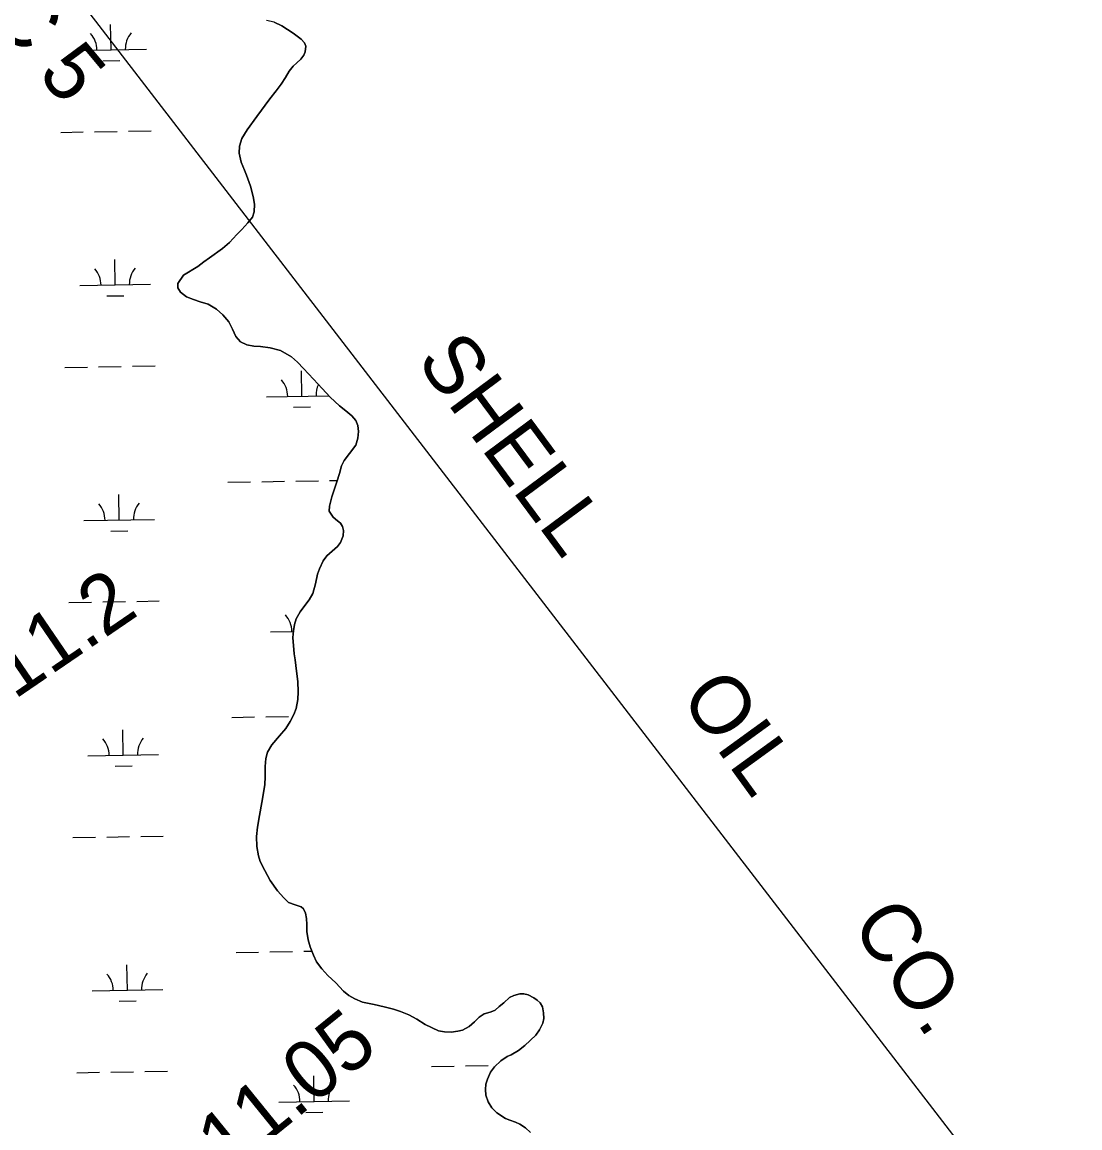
# Model space of a CAD drawing. Extents: x 3892998 to 3931244, y 278583 to 304547.
# Drawn here: x 3913620 to 3915117, y 291060 to 292624 of the extents above; entities that cross this region are included whole.
import ezdxf

# ---------------------------------------------------------------- set-up
doc = ezdxf.new("R2010")
doc.units = 0
for name, color, linetype in [('V-RIVR-EDGE', 7, 'Continuous'), ('V-RIVR-RANG-IDEN', 7, 'Continuous'), ('V-TOPO-SHOR', 7, 'Continuous'), ('V-UTIL-IDEN', 7, 'Continuous'), ('V-UTIL-LINE', 7, 'Continuous'), ('V-WETL-SWMP', 7, 'Continuous')]:
    doc.layers.add(name, color=color, linetype=linetype)

msp = doc.modelspace()

# ---------------------------------------------------------------- linework, layer by layer
at = {"layer": 'V-RIVR-EDGE'}
msp.add_spline([(3912905.5, 291820.1), (3912916.2, 291798.1), (3912921.4, 291787), (3912931.4, 291765), (3912935.9, 291747.6), (3912940.4, 291735.8), (3912955, 291711.4), (3912961.5, 291684.5), (3912964.3, 291665.7), (3912967, 291653.5), (3912976, 291634.4), (3912985.7, 291613.1), (3912986.4, 291604.4), (3912990.5, 291597.4), (3912997.1, 291593.3), (3913007.6, 291587), (3913014.2, 291580.7), (3913019.4, 291567.4), (3913027, 291556.3), (3913048.2, 291537.1), (3913061.4, 291520.7), (3913079.1, 291496.6), (3913103, 291468.4), (3913127.3, 291438.4), (3913184.9, 291379.7), (3913206.1, 291354.6), (3913225.2, 291327.8), (3913253.3, 291286.6), (3913265.1, 291274.8), (3913279.3, 291262.2), (3913304.7, 291231.5), (3913329.3, 291201.2), (3913355.7, 291168.4), (3913376.5, 291143.3), (3913400.8, 291111.5), (3913434.5, 291068.6), (3913468.5, 291022.2), (3913495.2, 290985.6), (3913514.6, 290959.1), (3913570.4, 290873.7), (3913590.9, 290842), (3913606.5, 290820.3), (3913627.3, 290792.1), (3913641.2, 290769.8), (3913669.6, 290726.2), (3913686.6, 290700.8), (3913705.7, 290679.5), (3913722, 290663.1), (3913741.1, 290638), (3913763.7, 290606.9), (3913781, 290589.5)], degree=3, dxfattribs=at)
at = {"layer": 'V-TOPO-SHOR'}
for points in [[(3913872.1, 292228.6), (3913862.7, 292231.7), (3913852.9, 292235.6), (3913844.3, 292242.1), (3913840.6, 292248.5), (3913840.3, 292254.7), (3913848.4, 292266.4), (3913868.7, 292278.5), (3913877.2, 292285), (3913885.1, 292291), (3913903.7, 292304), (3913913.4, 292312.7), (3913924, 292324), (3913930.9, 292331), (3913939.7, 292340.4), (3913946, 292348.3), (3913948.4, 292356), (3913948.7, 292366.6), (3913947, 292377.6), (3913943.3, 292392.2), (3913937.5, 292407.9), (3913934.6, 292414.9), (3913930.3, 292426.3), (3913927.3, 292439), (3913927.5, 292448.9), (3913931, 292459.6), (3913938.5, 292472.2), (3913952.2, 292490.9), (3913970.4, 292515.8), (3913979.7, 292527.1), (3913986.8, 292536.5), (3913992.8, 292546), (3913998.1, 292554.8), (3914003.8, 292562), (3914008.8, 292566.9), (3914014.3, 292571.9), (3914018.7, 292577.4), (3914020.7, 292582.4), (3914021.4, 292590.2), (3914019.5, 292595), (3914014.8, 292600.3), (3914003.7, 292608.8), (3913987.6, 292619.2), (3913976.7, 292624.4), (3913965.8, 292626.7)], [(3914075, 291253.5), (3914064, 291265), (3914052.9, 291275.6), (3914044.1, 291284.9), (3914036.9, 291294.8), (3914032.2, 291304), (3914027.6, 291315.8), (3914024.7, 291325.9), (3914023, 291337.8), (3914022.9, 291347.8), (3914022.7, 291356.2), (3914021.3, 291363.5), (3914018.5, 291369.7), (3914014.8, 291372.6), (3914006.6, 291375.3), (3913997.2, 291378.9), (3913990.5, 291385.4), (3913981.6, 291395.1), (3913970.9, 291409.8), (3913963.4, 291423.9), (3913956.9, 291436.7), (3913954.4, 291444.9), (3913952.2, 291458.1), (3913951.8, 291472.3), (3913953, 291485.3), (3913955.8, 291501.9), (3913959.5, 291520.1), (3913963.4, 291545), (3913964, 291557.1), (3913964.2, 291571.2), (3913965.2, 291582.3), (3913967.5, 291591.4), (3913973.4, 291601.6), (3913984.3, 291614.7), (3913993.2, 291624.9), (3913999.5, 291634.8), (3914004.8, 291644.5), (3914007.7, 291653), (3914010.1, 291666), (3914010.7, 291677), (3914010.4, 291691.5), (3914008.5, 291706.1), (3914006.3, 291721.9), (3914004.9, 291730.7), (3914003.3, 291753.8), (3914004, 291762.9), (3914005.4, 291771.9), (3914007.8, 291779.9), (3914013.4, 291789.8), (3914021.5, 291801), (3914026.5, 291807.1), (3914031.5, 291815.9), (3914035.2, 291829.5), (3914038.3, 291843.1), (3914041.1, 291850.9), (3914046.1, 291862.3), (3914051.4, 291869.3), (3914058.6, 291875.8), (3914066.2, 291882.4), (3914070.6, 291888.3), (3914074.4, 291897.7), (3914075, 291905.2), (3914073.6, 291910.6), (3914070.6, 291915.3), (3914066.4, 291918.9), (3914060.2, 291923.9), (3914054.8, 291932.2), (3914055.1, 291939.7), (3914058.3, 291952.6), (3914065.3, 291973.7), (3914069, 291985.7), (3914072.2, 291996.6), (3914075.6, 292004.3), (3914083.4, 292014), (3914092.1, 292025.7), (3914095.1, 292035.6), (3914095.9, 292045), (3914095.3, 292053.7), (3914092.4, 292060.9), (3914086.7, 292067.5), (3914078, 292074.4), (3914069.2, 292081.5), (3914055.9, 292093.9), (3914044.5, 292106.2), (3914032.5, 292119.3), (3914018.4, 292134.1), (3914009.6, 292143.2), (3914001.1, 292150.8), (3913985.6, 292159.7), (3913971.3, 292163.6), (3913957.6, 292165.2), (3913947.9, 292165.8), (3913938.2, 292167.8), (3913928.9, 292172.2), (3913922.6, 292179.5), (3913917.7, 292189.8), (3913912.6, 292200.2), (3913904.3, 292210.3), (3913895.3, 292218), (3913883.2, 292225.1), (3913872.1, 292228.6)], [(3914339.5, 291053.2), (3914332.5, 291059.8), (3914324.3, 291065.1), (3914318.1, 291068.1), (3914310.4, 291070.6), (3914304.1, 291073.2), (3914292, 291081), (3914284.7, 291088.3), (3914279.5, 291096.6), (3914276.5, 291106.2), (3914275.8, 291114), (3914276.5, 291121.6), (3914278.5, 291128.8), (3914283, 291138.7), (3914288.4, 291146.3), (3914297.5, 291154.5), (3914306.4, 291160.9), (3914312.2, 291163.4), (3914322.4, 291169.2), (3914331.5, 291176.4), (3914346.9, 291191), (3914352.4, 291198.7), (3914357, 291208.1), (3914358.3, 291214.5), (3914358.1, 291222.7), (3914356.4, 291230.9), (3914353.3, 291236.8), (3914349.1, 291240.6), (3914344.2, 291244), (3914336.4, 291248), (3914329.9, 291249.7), (3914324.4, 291249.4), (3914316.1, 291247), (3914310, 291244.3), (3914301.6, 291237), (3914295.2, 291231.4), (3914289.4, 291226.6), (3914284, 291224.1), (3914279.1, 291222.8), (3914273.7, 291221), (3914266.9, 291216.6), (3914260.2, 291209.9), (3914252.5, 291203.3), (3914243.4, 291198), (3914236.8, 291196.5), (3914227.4, 291195.4), (3914218, 291195.8), (3914209.4, 291197.2), (3914190.6, 291205.9), (3914178.8, 291213.5), (3914167.3, 291219.9), (3914155.6, 291224.7), (3914145.8, 291228), (3914132.4, 291230.9), (3914118.4, 291234.2), (3914101.9, 291237.9), (3914090.7, 291242.3), (3914082.2, 291247.3), (3914075, 291253.5)]]:
    msp.add_lwpolyline(points, dxfattribs=at)
at = {"layer": 'V-UTIL-LINE'}
msp.add_lwpolyline([(3906680.9, 302363.5), (3908344.9, 300090), (3912732.6, 293653.7), (3913646.8, 292726.8), (3916248.7, 289346), (3918159.9, 287579.4), (3921518.3, 284435.1)], dxfattribs=at)
at = {"layer": 'V-WETL-SWMP'}
for p, q in [((3913746.1, 292585.1), (3913745.4, 292621.1)), ((3913976.7, 292624.4), (3913987.6, 292619.2)), ((3913987.6, 292619.2), (3914003.7, 292608.8)), ((3914003.7, 292608.8), (3914014.8, 292600.3)), ((3914014.8, 292600.3), (3914019.5, 292595)), ((3914019.5, 292595), (3914021.4, 292590.2)), ((3914021.4, 292590.2), (3914020.7, 292582.4)), ((3913696.1, 292584.3), (3913796.1, 292586)), ((3914014.3, 292571.9), (3914008.8, 292566.9)), ((3914018.7, 292577.4), (3914014.3, 292571.9)), ((3914020.7, 292582.4), (3914018.7, 292577.4)), ((3913734.3, 292569.5), (3913758.3, 292569.9)), ((3914003.8, 292562), (3913998.1, 292554.8)), ((3914008.8, 292566.9), (3914003.8, 292562)), ((3913992.8, 292546), (3913986.8, 292536.5)), ((3913998.1, 292554.8), (3913992.8, 292546)), ((3913979.7, 292527.1), (3913970.4, 292515.8)), ((3913986.8, 292536.5), (3913979.7, 292527.1)), ((3913970.4, 292515.8), (3913952.2, 292490.9)), ((3913952.2, 292490.9), (3913938.5, 292472.2)), ((3913674.7, 292468.4), (3913706.7, 292469)), ((3913722.7, 292469.3), (3913754.7, 292469.8)), ((3913770.7, 292470.1), (3913802.6, 292470.6)), ((3913938.5, 292472.2), (3913931, 292459.6)), ((3913927.5, 292448.9), (3913927.3, 292439)), ((3913931, 292459.6), (3913927.5, 292448.9)), ((3913927.3, 292439), (3913930.3, 292426.3)), ((3913930.3, 292426.3), (3913934.6, 292414.9)), ((3913934.6, 292414.9), (3913937.5, 292407.9)), ((3913937.5, 292407.9), (3913943.3, 292392.2)), ((3913943.3, 292392.2), (3913947, 292377.6)), ((3913947, 292377.6), (3913948.7, 292366.6)), ((3913948.4, 292356), (3913946, 292348.3)), ((3913948.7, 292366.6), (3913948.4, 292356)), ((3913939.7, 292340.4), (3913930.9, 292331)), ((3913946, 292348.3), (3913939.7, 292340.4)), ((3913924, 292324), (3913913.4, 292312.7)), ((3913930.9, 292331), (3913924, 292324)), ((3913913.4, 292312.7), (3913903.7, 292304)), ((3913905.5, 292305.9), (3913905.8, 292305.9)), ((3913885.1, 292291), (3913877.2, 292285)), ((3913903.7, 292304), (3913885.1, 292291)), ((3913751.8, 292252.5), (3913751.2, 292288.5)), ((3913868.7, 292278.5), (3913848.4, 292266.4)), ((3913877.2, 292285), (3913868.7, 292278.5)), ((3913848.4, 292266.4), (3913840.3, 292254.7)), ((3913701.8, 292251.6), (3913801.8, 292253.4)), ((3913840.3, 292254.7), (3913840.6, 292248.5)), ((3913840.6, 292248.5), (3913844.3, 292242.1)), ((3913740.1, 292236.9), (3913764.1, 292237.3)), ((3913844.3, 292242.1), (3913852.9, 292235.6)), ((3913852.9, 292235.6), (3913862.7, 292231.7)), ((3913862.7, 292231.7), (3913872.1, 292228.6)), ((3913872.1, 292228.6), (3913883.2, 292225.1)), ((3913883.2, 292225.1), (3913895.3, 292218)), ((3913895.3, 292218), (3913904.3, 292210.3)), ((3913904.3, 292210.3), (3913912.6, 292200.2)), ((3913912.6, 292200.2), (3913917.7, 292189.8)), ((3913917.7, 292189.8), (3913922.6, 292179.5)), ((3913922.6, 292179.5), (3913928.9, 292172.2)), ((3913928.9, 292172.2), (3913938.2, 292167.8)), ((3913938.2, 292167.8), (3913947.9, 292165.8)), ((3913947.9, 292165.8), (3913957.6, 292165.2)), ((3913957.6, 292165.2), (3913971.3, 292163.6)), ((3913971.3, 292163.6), (3913985.6, 292159.7)), ((3913985.6, 292159.7), (3914001.1, 292150.8)), ((3914001.1, 292150.8), (3914009.6, 292143.2)), ((3913680.4, 292135.8), (3913712.4, 292136.4)), ((3913728.4, 292136.6), (3913760.4, 292137.2)), ((3913776.4, 292137.5), (3913808.4, 292138)), ((3914009.6, 292143.2), (3914018.4, 292134.1)), ((3914018.4, 292134.1), (3914032.5, 292119.3)), ((3914016, 292095.2), (3914015.4, 292131.2)), ((3914032.5, 292119.3), (3914044.5, 292106.2)), ((3914044.5, 292106.2), (3914055.9, 292093.9)), ((3913966, 292094.3), (3914054.1, 292095.8)), ((3914055.9, 292093.9), (3914069.2, 292081.5)), ((3914004.3, 292079.5), (3914028.3, 292080)), ((3914069.2, 292081.5), (3914078, 292074.4)), ((3914078, 292074.4), (3914086.7, 292067.5)), ((3914086.7, 292067.5), (3914092.4, 292060.9)), ((3914092.4, 292060.9), (3914095.3, 292053.7)), ((3914095.9, 292045), (3914095.1, 292035.6)), ((3914095.3, 292053.7), (3914095.9, 292045)), ((3914092.1, 292025.7), (3914083.4, 292014)), ((3914095.1, 292035.6), (3914092.1, 292025.7)), ((3914083.4, 292014), (3914075.6, 292004.3)), ((3914072.2, 291996.6), (3914069, 291985.7)), ((3914075.6, 292004.3), (3914072.2, 291996.6)), ((3914069, 291985.7), (3914065.3, 291973.7)), ((3913911.3, 291973.3), (3913943.3, 291973.8)), ((3913959.3, 291974.1), (3913991.3, 291974.7)), ((3914007.3, 291974.9), (3914039.3, 291975.5)), ((3914055.2, 291975.8), (3914066, 291976)), ((3914065.3, 291973.7), (3914058.3, 291952.6)), ((3913757.6, 291919.9), (3913757, 291955.9)), ((3914058.3, 291952.6), (3914055.1, 291939.7)), ((3914055.1, 291939.7), (3914054.8, 291932.2)), ((3914054.8, 291932.2), (3914060.2, 291923.9)), ((3913707.6, 291919), (3913807.6, 291920.7)), ((3914060.2, 291923.9), (3914066.4, 291918.9)), ((3914066.4, 291918.9), (3914070.6, 291915.3)), ((3914070.6, 291915.3), (3914073.6, 291910.6)), ((3913745.8, 291904.2), (3913769.8, 291904.6)), ((3914073.6, 291910.6), (3914075, 291905.2)), ((3914075, 291905.2), (3914074.4, 291897.7)), ((3914070.6, 291888.3), (3914066.2, 291882.4)), ((3914074.4, 291897.7), (3914070.6, 291888.3)), ((3914051.4, 291869.3), (3914046.1, 291862.3)), ((3914058.6, 291875.8), (3914051.4, 291869.3)), ((3914066.2, 291882.4), (3914058.6, 291875.8)), ((3914046.1, 291862.3), (3914041.1, 291850.9)), ((3914038.3, 291843.1), (3914035.2, 291829.5)), ((3914041.1, 291850.9), (3914038.3, 291843.1)), ((3914035.2, 291829.5), (3914031.5, 291815.9)), ((3913734.2, 291804), (3913766.2, 291804.6)), ((3913782.2, 291804.8), (3913814.2, 291805.4)), ((3914026.5, 291807.1), (3914021.5, 291801)), ((3914031.5, 291815.9), (3914026.5, 291807.1)), ((3913686.2, 291803.2), (3913718.2, 291803.7)), ((3914013.4, 291789.8), (3914007.8, 291779.9)), ((3914021.5, 291801), (3914013.4, 291789.8)), ((3914007.8, 291779.9), (3914005.4, 291771.9)), ((3913971.8, 291761.7), (3914003.9, 291762.2)), ((3914004, 291762.9), (3914003.3, 291753.8)), ((3914005.4, 291771.9), (3914004, 291762.9)), ((3914003.3, 291753.8), (3914004.9, 291730.7)), ((3914004.9, 291730.7), (3914006.3, 291721.9)), ((3914006.3, 291721.9), (3914008.5, 291706.1)), ((3914008.5, 291706.1), (3914010.4, 291691.5)), ((3914010.4, 291691.5), (3914010.7, 291677)), ((3914010.1, 291666), (3914007.7, 291653)), ((3914010.7, 291677), (3914010.1, 291666)), ((3914007.7, 291653), (3914004.8, 291644.5)), ((3913917, 291640.7), (3913949, 291641.2)), ((3913965, 291641.5), (3913997, 291642)), ((3913999.5, 291634.8), (3913993.2, 291624.9)), ((3914004.8, 291644.5), (3913999.5, 291634.8)), ((3913763.3, 291587.2), (3913762.7, 291623.2)), ((3913993.2, 291624.9), (3913984.3, 291614.7)), ((3913973.4, 291601.6), (3913967.5, 291591.4)), ((3913984.3, 291614.7), (3913973.4, 291601.6)), ((3913713.3, 291586.4), (3913813.3, 291588.1)), ((3913967.5, 291591.4), (3913965.2, 291582.3)), ((3913751.6, 291571.6), (3913775.6, 291572)), ((3913964.2, 291571.2), (3913964, 291557.1)), ((3913965.2, 291582.3), (3913964.2, 291571.2)), ((3913964, 291557.1), (3913963.4, 291545)), ((3913963.4, 291545), (3913959.5, 291520.1)), ((3913959.5, 291520.1), (3913955.8, 291501.9)), ((3913955.8, 291501.9), (3913953, 291485.3)), ((3913953, 291485.3), (3913951.8, 291472.3)), ((3913691.9, 291470.6), (3913723.9, 291471.1)), ((3913739.9, 291471.4), (3913771.9, 291471.9)), ((3913787.9, 291472.2), (3913819.9, 291472.8)), ((3913951.8, 291472.3), (3913952.2, 291458.1)), ((3913952.2, 291458.1), (3913954.4, 291444.9)), ((3913954.4, 291444.9), (3913956.9, 291436.7)), ((3913956.9, 291436.7), (3913963.4, 291423.9)), ((3913963.4, 291423.9), (3913970.9, 291409.8)), ((3913970.9, 291409.8), (3913981.6, 291395.1)), ((3913981.6, 291395.1), (3913990.5, 291385.4)), ((3913990.5, 291385.4), (3913997.2, 291378.9)), ((3913997.2, 291378.9), (3914006.6, 291375.3)), ((3914006.6, 291375.3), (3914014.8, 291372.6)), ((3914014.8, 291372.6), (3914018.5, 291369.7)), ((3914018.5, 291369.7), (3914021.3, 291363.5)), ((3914021.3, 291363.5), (3914022.7, 291356.2)), ((3914022.7, 291356.2), (3914022.9, 291347.8)), ((3914022.9, 291347.8), (3914023, 291337.8)), ((3914023, 291337.8), (3914024.7, 291325.9)), ((3914024.7, 291325.9), (3914027.6, 291315.8)), ((3913922.8, 291308), (3913954.8, 291308.6)), ((3913970.8, 291308.9), (3914002.8, 291309.4)), ((3914018.8, 291309.7), (3914029.9, 291309.9)), ((3914027.6, 291315.8), (3914032.2, 291304)), ((3914032.2, 291304), (3914036.9, 291294.8)), ((3913769.1, 291254.6), (3913768.5, 291290.6)), ((3914036.9, 291294.8), (3914044.1, 291284.9)), ((3914044.1, 291284.9), (3914052.9, 291275.6)), ((3914052.9, 291275.6), (3914064, 291265)), ((3914064, 291265), (3914075, 291253.5)), ((3913719.1, 291253.8), (3913819.1, 291255.5)), ((3914075, 291253.5), (3914082.2, 291247.3)), ((3914082.2, 291247.3), (3914090.7, 291242.3)), ((3914090.7, 291242.3), (3914101.9, 291237.9)), ((3914301.6, 291237), (3914310, 291244.3)), ((3914310, 291244.3), (3914316.1, 291247)), ((3914316.1, 291247), (3914324.4, 291249.4)), ((3914324.4, 291249.4), (3914329.9, 291249.7)), ((3914329.9, 291249.7), (3914336.4, 291248)), ((3914336.4, 291248), (3914344.2, 291244)), ((3914344.2, 291244), (3914349.1, 291240.6)), ((3913757.4, 291239), (3913781.4, 291239.4)), ((3914101.9, 291237.9), (3914118.4, 291234.2)), ((3914118.4, 291234.2), (3914132.4, 291230.9)), ((3914132.4, 291230.9), (3914145.8, 291228)), ((3914145.8, 291228), (3914155.6, 291224.7)), ((3914284, 291224.1), (3914289.4, 291226.6)), ((3914289.4, 291226.6), (3914295.2, 291231.4)), ((3914295.2, 291231.4), (3914301.6, 291237)), ((3914349.1, 291240.6), (3914353.3, 291236.8)), ((3914353.3, 291236.8), (3914356.4, 291230.9)), ((3914356.4, 291230.9), (3914358.1, 291222.7)), ((3914155.6, 291224.7), (3914167.3, 291219.9)), ((3914167.3, 291219.9), (3914178.8, 291213.5)), ((3914178.8, 291213.5), (3914190.6, 291205.9)), ((3914252.5, 291203.3), (3914260.2, 291209.9)), ((3914260.2, 291209.9), (3914266.9, 291216.6)), ((3914266.9, 291216.6), (3914273.7, 291221)), ((3914273.7, 291221), (3914279.1, 291222.8)), ((3914279.1, 291222.8), (3914284, 291224.1)), ((3914358.3, 291214.5), (3914357, 291208.1)), ((3914358.1, 291222.7), (3914358.3, 291214.5)), ((3914190.6, 291205.9), (3914209.4, 291197.2)), ((3914209.4, 291197.2), (3914218, 291195.8)), ((3914218, 291195.8), (3914227.4, 291195.4)), ((3914227.4, 291195.4), (3914236.8, 291196.5)), ((3914236.8, 291196.5), (3914243.4, 291198)), ((3914243.4, 291198), (3914252.5, 291203.3)), ((3914352.4, 291198.7), (3914346.9, 291191)), ((3914357, 291208.1), (3914352.4, 291198.7)), ((3914346.9, 291191), (3914331.5, 291176.4)), ((3914312.2, 291163.4), (3914306.4, 291160.9)), ((3914322.4, 291169.2), (3914312.2, 291163.4)), ((3914331.5, 291176.4), (3914322.4, 291169.2)), ((3914199.5, 291146.6), (3914231.5, 291147.2)), ((3914247.5, 291147.5), (3914279.5, 291148)), ((3914297.5, 291154.5), (3914288.4, 291146.3)), ((3914306.4, 291160.9), (3914297.5, 291154.5)), ((3913697.7, 291137.9), (3913729.7, 291138.5)), ((3913745.7, 291138.8), (3913777.7, 291139.3)), ((3913793.7, 291139.6), (3913825.7, 291140.1)), ((3914033.3, 291097.3), (3914032.7, 291133.3)), ((3914283, 291138.7), (3914278.5, 291128.8)), ((3914288.4, 291146.3), (3914283, 291138.7)), ((3914276.5, 291121.6), (3914275.8, 291114)), ((3914278.5, 291128.8), (3914276.5, 291121.6)), ((3914275.8, 291114), (3914276.5, 291106.2)), ((3914276.5, 291106.2), (3914279.5, 291096.6)), ((3913983.3, 291096.4), (3914083.3, 291098.2)), ((3914279.5, 291096.6), (3914284.7, 291088.3)), ((3914284.7, 291088.3), (3914292, 291081)), ((3914021.6, 291081.7), (3914045.6, 291082.1)), ((3914292, 291081), (3914304.1, 291073.2)), ((3914304.1, 291073.2), (3914310.4, 291070.6)), ((3914310.4, 291070.6), (3914318.1, 291068.1)), ((3914318.1, 291068.1), (3914324.3, 291065.1)), ((3914324.3, 291065.1), (3914332.5, 291059.8))]:
    msp.add_line(p, q, dxfattribs=at)
for centre, start, end in [((3913690.8, 292584.6), 0.2199, 41.7635), ((3913801.3, 292586.6), 140.2199, 181.7635), ((3913696.6, 292252), 0.2199, 41.7635), ((3913807, 292253.9), 140.2199, 181.7635), ((3913960.8, 292094.7), 0.2199, 41.7635), ((3914071.2, 292096.6), 154.607, 181.7635), ((3913702.3, 291919.4), 0.2199, 41.7635), ((3913812.8, 291921.3), 140.2199, 181.7635), ((3913966.5, 291762.1), 0.2199, 41.7635), ((3913708.1, 291586.8), 0.2199, 41.7635), ((3913818.6, 291588.7), 140.2199, 181.7635), ((3913713.9, 291254.1), 0.2199, 41.7635), ((3913824.3, 291256), 140.2199, 181.7635), ((3913978.1, 291096.8), 0.2199, 41.7635), ((3914088.5, 291098.7), 140.2199, 181.7635)]:
    msp.add_arc(centre, 35.2, start, end, dxfattribs=at)

# ---------------------------------------------------------------- texts
at = {"layer": 'V-RIVR-RANG-IDEN'}
for s, rotation, p in [('R-BC 5', 309.7794, (3913447.5, 292783.2)), ('R-11.2', 34.3312, (3913512.3, 291599)), ('R-11.05', 39.0186, (3913820.5, 290920.5))]:
    msp.add_text(s, height=83, rotation=rotation, dxfattribs=at).set_placement(p)
at = {"layer": 'V-UTIL-IDEN'}
for s, rotation, p in [('SHELL', 306.5584, (3914176.6, 292145.1)), ('OIL', 305.9497, (3914549.7, 291668.6)), ('CO.', 303.9497, (3914792.2, 291347.6))]:
    msp.add_text(s, height=83, rotation=rotation, dxfattribs=at).set_placement(p)

doc.saveas('drawing.dxf')
